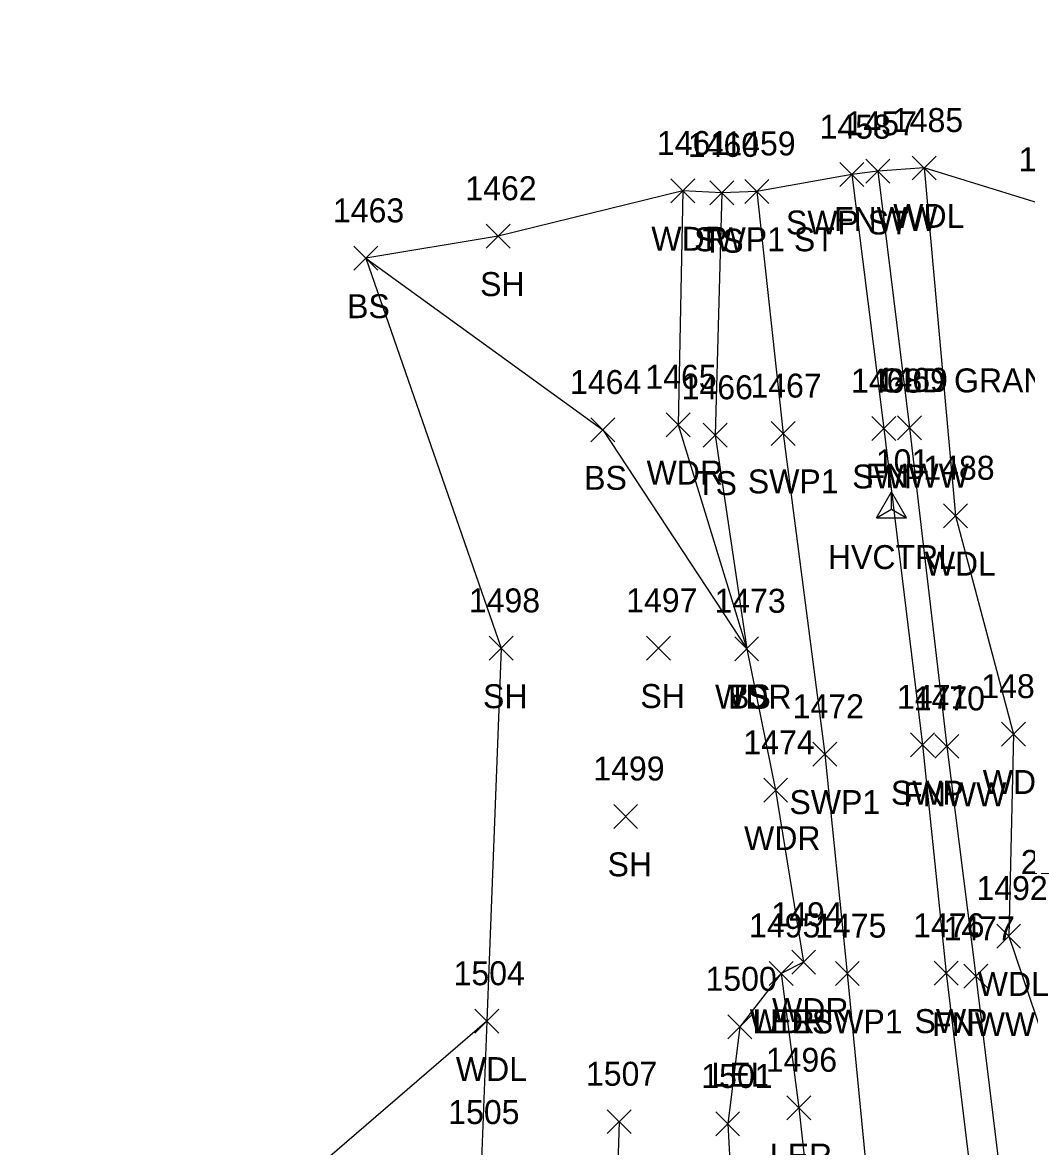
# Model space of a CAD drawing. Extents: x 1638344 to 1639591, y 610835 to 612202.
# Drawn here: x 1638553.3 to 1638637.1, y 611741.3 to 611835.2 of the extents above; entities that cross this region are included whole.
import ezdxf

# ---------------------------------------------------------------- set-up
doc = ezdxf.new("R2010")
doc.units = 0
for name, color, linetype in [('C_A', 7, 'Continuous'), ('C_I', 7, 'Continuous'), ('CPSM', 7, 'Continuous'), ('L_A', 7, 'Continuous'), ('L_C', 7, 'Continuous'), ('L_I', 7, 'Continuous'), ('L_TIC', 7, 'Continuous'), ('LARO', 7, 'Continuous'), ('LAWA', 7, 'Continuous'), ('LELB', 7, 'Continuous'), ('LFNC', 7, 'Continuous'), ('LSOGP', 7, 'Continuous'), ('R_A', 7, 'Continuous'), ('R_I', 7, 'Continuous'), ('R_TIC', 7, 'Continuous'), ('RTRP', 7, 'Continuous')]:
    doc.layers.add(name, color=color, linetype=linetype)

msp = doc.modelspace()

# ---------------------------------------------------------------- linework, layer by layer
at = {"layer": 'CPSM'}
for p, q in [((1638624.599, 611793.804), (1638625.849, 611795.969)), ((1638627.099, 611793.804), (1638625.849, 611795.969)), ((1638625.849, 611794.525), (1638625.849, 611795.969)), ((1638624.599, 611793.804), (1638625.849, 611794.525)), ((1638625.849, 611794.525), (1638625.849, 611794.525)), ((1638625.849, 611794.525), (1638627.099, 611793.804)), ((1638624.599, 611793.804), (1638627.099, 611793.804))]:
    msp.add_line(p, q, dxfattribs=at)
at = {"layer": 'L_TIC'}
for points in [[(1638623.708, 611821.742), (1638625.708, 611823.742)], [(1638625.708, 611821.742), (1638623.708, 611823.742)], [(1638627.579, 611822.011), (1638629.579, 611824.011)], [(1638629.579, 611822.011), (1638627.579, 611824.011)], [(1638607.438, 611820.099), (1638609.438, 611822.099)], [(1638609.438, 611820.099), (1638607.438, 611822.099)], [(1638610.675, 611819.94), (1638612.675, 611821.94)], [(1638612.675, 611819.94), (1638610.675, 611821.94)], [(1638592.01, 611816.319), (1638594.01, 611818.319)], [(1638594.01, 611816.319), (1638592.01, 611818.319)], [(1638580.952, 611814.473), (1638582.952, 611816.473)], [(1638582.952, 611814.473), (1638580.952, 611816.473)], [(1638600.75, 611800.142), (1638602.75, 611802.142)], [(1638602.75, 611800.142), (1638600.75, 611802.142)], [(1638607.038, 611800.578), (1638609.038, 611802.578)], [(1638609.038, 611800.578), (1638607.038, 611802.578)], [(1638626.359, 611800.327), (1638628.359, 611802.327)], [(1638628.359, 611800.327), (1638626.359, 611802.327)], [(1638610.122, 611799.702), (1638612.122, 611801.702)], [(1638612.122, 611799.702), (1638610.122, 611801.702)], [(1638630.205, 611792.982), (1638632.205, 611794.982)], [(1638632.205, 611792.982), (1638630.205, 611794.982)], [(1638592.253, 611781.913), (1638594.253, 611783.913)], [(1638594.253, 611781.913), (1638592.253, 611783.913)], [(1638605.394, 611781.927), (1638607.394, 611783.927)], [(1638607.394, 611781.927), (1638605.394, 611783.927)], [(1638612.759, 611781.879), (1638614.759, 611783.879)], [(1638614.759, 611781.879), (1638612.759, 611783.879)], [(1638612.759, 611781.879), (1638614.759, 611783.879)], [(1638614.759, 611781.879), (1638612.759, 611783.879)], [(1638612.759, 611781.879), (1638614.759, 611783.879)], [(1638614.759, 611781.879), (1638612.759, 611783.879)], [(1638635.051, 611774.752), (1638637.051, 611776.752)], [(1638637.051, 611774.752), (1638635.051, 611776.752)], [(1638629.484, 611773.727), (1638631.484, 611775.727)], [(1638631.484, 611773.727), (1638629.484, 611775.727)], [(1638615.178, 611770.061), (1638617.178, 611772.061)], [(1638617.178, 611770.061), (1638615.178, 611772.061)], [(1638602.655, 611767.877), (1638604.655, 611769.877)], [(1638604.655, 611767.877), (1638602.655, 611769.877)], [(1638634.636, 611757.892), (1638636.636, 611759.892)], [(1638636.636, 611757.892), (1638634.636, 611759.892)], [(1638617.516, 611755.711), (1638619.516, 611757.711)], [(1638619.516, 611755.711), (1638617.516, 611757.711)], [(1638615.65, 611754.775), (1638617.65, 611756.775)], [(1638617.65, 611754.775), (1638615.65, 611756.775)], [(1638615.65, 611754.775), (1638617.65, 611756.775)], [(1638617.65, 611754.775), (1638615.65, 611756.775)], [(1638615.65, 611754.775), (1638617.65, 611756.775)], [(1638617.65, 611754.775), (1638615.65, 611756.775)], [(1638631.894, 611754.534), (1638633.894, 611756.534)], [(1638633.894, 611754.534), (1638631.894, 611756.534)], [(1638591.058, 611750.785), (1638593.058, 611752.785)], [(1638593.058, 611750.785), (1638591.058, 611752.785)], [(1638612.184, 611750.321), (1638614.184, 611752.321)], [(1638614.184, 611750.321), (1638612.184, 611752.321)], [(1638617.104, 611743.559), (1638619.104, 611745.559)], [(1638619.104, 611743.559), (1638617.104, 611745.559)], [(1638602.11, 611742.393), (1638604.11, 611744.393)], [(1638604.11, 611742.393), (1638602.11, 611744.393)], [(1638611.172, 611742.208), (1638613.172, 611744.208)], [(1638613.172, 611742.208), (1638611.172, 611744.208)]]:
    msp.add_lwpolyline(points, dxfattribs=at)
at = {"layer": 'LARO'}
for points in [[(1638616.65, 611755.775), (1638613.184, 611751.321), (1638612.172, 611743.208), (1638612.857, 611730.745), (1638612.87, 611721.16), (1638597.248, 611704.003), (1638583.675, 611698.565), (1638570.67, 611686.127)], [(1638616.65, 611755.775), (1638618.104, 611744.559), (1638619.344, 611733.411), (1638619.709, 611721.561), (1638618.446, 611708.332), (1638614.45, 611704.873)]]:
    msp.add_lwpolyline(points, dxfattribs=at)
at = {"layer": 'LAWA'}
for points in [[(1638628.579, 611823.011), (1638631.205, 611793.982), (1638636.051, 611775.752), (1638635.636, 611758.892), (1638640.82, 611743.59), (1638643.87, 611738.789), (1638644.553, 611728.051), (1638647.989, 611718.924), (1638655.164, 611720.387)], [(1638608.438, 611821.099), (1638608.038, 611801.578), (1638613.759, 611782.879), (1638616.178, 611771.061), (1638618.516, 611756.711), (1638616.65, 611755.775)], [(1638592.058, 611751.785), (1638591.611, 611740.196), (1638589.923, 611720.382), (1638576.635, 611709.157), (1638568.384, 611698.67), (1638553.288, 611683.216), (1638569.948, 611678.542), (1638575.99, 611681.669)]]:
    msp.add_lwpolyline(points, dxfattribs=at)
at = {"layer": 'LELB'}
for points in [[(1638611.675, 611820.94), (1638611.122, 611800.702), (1638613.759, 611782.879)], [(1638581.952, 611815.473), (1638601.75, 611801.142), (1638613.759, 611782.879)], [(1638603.11, 611743.393), (1638602.559, 611725.8), (1638601.411, 611714.442)]]:
    msp.add_lwpolyline(points, dxfattribs=at)
at = {"layer": 'LFNC'}
msp.add_lwpolyline([(1638624.708, 611822.742), (1638627.359, 611801.327), (1638630.484, 611774.727), (1638632.894, 611755.534), (1638636.54, 611725.742)], dxfattribs=at)
at = {"layer": 'LSOGP'}
msp.add_lwpolyline([(1638742.435, 611835.158), (1638718.339, 611821.861), (1638715.698, 611824.36), (1638711.099, 611825.207), (1638697.729, 611820.746), (1638689.906, 611823.394), (1638677.812, 611825.266), (1638670.59, 611829.25), (1638668.561, 611829.322), (1638661.879, 611825.565), (1638654.744, 611821.976), (1638647.991, 611816.714), (1638639.216, 611819.73), (1638628.579, 611823.011), (1638624.708, 611822.742), (1638622.542, 611822.46), (1638614.597, 611821.058), (1638611.675, 611820.94), (1638608.438, 611821.099), (1638593.01, 611817.319), (1638581.952, 611815.473), (1638593.253, 611782.913), (1638592.058, 611751.785), (1638571.096, 611733.73)], dxfattribs=at)
at = {"layer": 'R_TIC'}
for points in [[(1638621.542, 611821.46), (1638623.542, 611823.46)], [(1638623.542, 611821.46), (1638621.542, 611823.46)], [(1638613.597, 611820.058), (1638615.597, 611822.058)], [(1638615.597, 611820.058), (1638613.597, 611822.058)], [(1638624.21, 611800.256), (1638626.21, 611802.256)], [(1638626.21, 611800.256), (1638624.21, 611802.256)], [(1638615.814, 611799.843), (1638617.814, 611801.843)], [(1638617.814, 611799.843), (1638615.814, 611801.843)], [(1638627.439, 611773.86), (1638629.439, 611775.86)], [(1638629.439, 611773.86), (1638627.439, 611775.86)], [(1638619.291, 611773.073), (1638621.291, 611775.073)], [(1638621.291, 611773.073), (1638619.291, 611775.073)], [(1638621.164, 611754.755), (1638623.164, 611756.755)], [(1638623.164, 611754.755), (1638621.164, 611756.755)], [(1638629.413, 611754.789), (1638631.413, 611756.789)], [(1638631.413, 611754.789), (1638629.413, 611756.789)]]:
    msp.add_lwpolyline(points, dxfattribs=at)
at = {"layer": 'RTRP'}
for p, q in [((1638614.597, 611821.058), (1638616.814, 611800.843)), ((1638616.814, 611800.843), (1638620.291, 611774.073)), ((1638620.291, 611774.073), (1638622.164, 611755.755)), ((1638622.164, 611755.755), (1638624.365, 611733.162))]:
    msp.add_line(p, q, dxfattribs=at)
msp.add_lwpolyline([(1638622.542, 611822.46), (1638625.21, 611801.256), (1638628.439, 611774.86), (1638630.413, 611755.789), (1638634.003, 611726.196), (1638635.63, 611712.905), (1638636.309, 611711.366), (1638637.432, 611709.925), (1638638.9, 611709.272), (1638643.391, 611710.611)], dxfattribs=at)

# ---------------------------------------------------------------- texts
at = {"layer": 'C_A'}
msp.add_text('HVCTRL', height=2, dxfattribs=at).set_placement((1638620.542, 611789.525))
at = {"layer": 'C_I'}
msp.add_text('101', height=2, dxfattribs=at).set_placement((1638624.542, 611797.525))
at = {"layer": 'L_A'}
for s, p in [('WDL', (1638625.996, 611818.011)), ('FNWW', (1638621.055, 611817.742)), ('WDR', (1638605.8, 611816.099)), ('TS', (1638610.085, 611815.94)), ('SH', (1638591.498, 611812.319)), ('BS', (1638580.393, 611810.473)), ('WDR', (1638605.4, 611796.578)), ('FNWW', (1638623.706, 611796.327)), ('BS', (1638600.191, 611796.142)), ('TS', (1638609.532, 611795.702)), ('WDL', (1638628.622, 611788.982)), ('SH', (1638591.741, 611777.913)), ('SH', (1638604.882, 611777.927)), ('WDR', (1638611.121, 611777.879)), ('TS', (1638612.168, 611777.879)), ('BS', (1638612.2, 611777.879)), ('WDL', (1638633.468, 611770.752)), ('FNWW', (1638626.831, 611769.727)), ('WDR', (1638613.54, 611766.061)), ('SH', (1638602.143, 611763.877)), ('WDL', (1638633.053, 611753.892)), ('WDR', (1638615.878, 611751.711)), ('WDR', (1638614.012, 611750.775)), ('LER', (1638614.233, 611750.775)), ('LEL', (1638614.288, 611750.775)), ('FNWW', (1638629.241, 611750.534)), ('WDL', (1638589.475, 611746.785)), ('LEL', (1638610.822, 611746.321)), ('LER', (1638615.686, 611739.559))]:
    msp.add_text(s, height=2, dxfattribs=at).set_placement(p)
at = {"layer": 'L_C'}
msp.add_text('OLD GRANITE BLOCK RETAINING', height=2, dxfattribs=at).set_placement((1638624.829, 611804.277))
at = {"layer": 'L_I'}
for s, p in [('1457', (1638622.015, 611825.742)), ('1485', (1638625.886, 611826.011)), ('1461', (1638606.264, 611824.099)), ('1460', (1638608.848, 611823.94)), ('1486', (1638636.468, 611822.73)), ('1462', (1638590.27, 611820.319)), ('1463', (1638579.212, 611818.473)), ('1464', (1638599.01, 611804.142)), ('1465', (1638605.298, 611804.578)), ('1469', (1638624.611, 611804.327)), ('1466', (1638608.327, 611803.702)), ('1488', (1638628.512, 611796.982)), ('1498', (1638590.56, 611785.913)), ('1497', (1638603.701, 611785.927)), ('1473', (1638611.066, 611785.879)), ('1473', (1638611.066, 611785.879)), ('1473', (1638611.066, 611785.879)), ('1489', (1638633.35, 611778.752)), ('1470', (1638627.705, 611777.727)), ('1474', (1638613.485, 611774.061)), ('1499', (1638600.954, 611771.877)), ('2176', (1638636.653, 611764.074)), ('1492', (1638632.943, 611761.892)), ('1494', (1638615.823, 611759.711)), ('1495', (1638613.957, 611758.775)), ('1495', (1638613.957, 611758.775)), ('1495', (1638613.957, 611758.775)), ('1477', (1638630.202, 611758.534)), ('1504', (1638589.286, 611754.785)), ('1500', (1638610.325, 611754.321)), ('1496', (1638615.356, 611747.559)), ('1507', (1638600.338, 611746.393)), ('1501', (1638609.968, 611746.208)), ('1505', (1638588.839, 611743.196))]:
    msp.add_text(s, height=2, dxfattribs=at).set_placement(p)
at = {"layer": 'R_A'}
for s, p in [('SWP ST', (1638617.038, 611817.46)), ('SWP1 ST', (1638609.377, 611816.058)), ('SWP', (1638622.573, 611796.256)), ('SWP1', (1638613.853, 611795.843)), ('SWP1', (1638617.33, 611769.073)), ('SWP', (1638625.801, 611769.86)), ('SWP1', (1638619.203, 611750.755)), ('SWP', (1638627.775, 611750.789))]:
    msp.add_text(s, height=2, dxfattribs=at).set_placement(p)
at = {"layer": 'R_I'}
for s, p in [('1458', (1638619.849, 611825.46)), ('1459', (1638611.896, 611824.058)), ('1467', (1638614.074, 611803.843)), ('1468', (1638622.47, 611804.256)), ('1471', (1638626.313, 611777.86)), ('1472', (1638617.598, 611777.073)), ('1475', (1638619.471, 611758.755)), ('1476', (1638627.665, 611758.789))]:
    msp.add_text(s, height=2, dxfattribs=at).set_placement(p)

doc.saveas('drawing.dxf')
